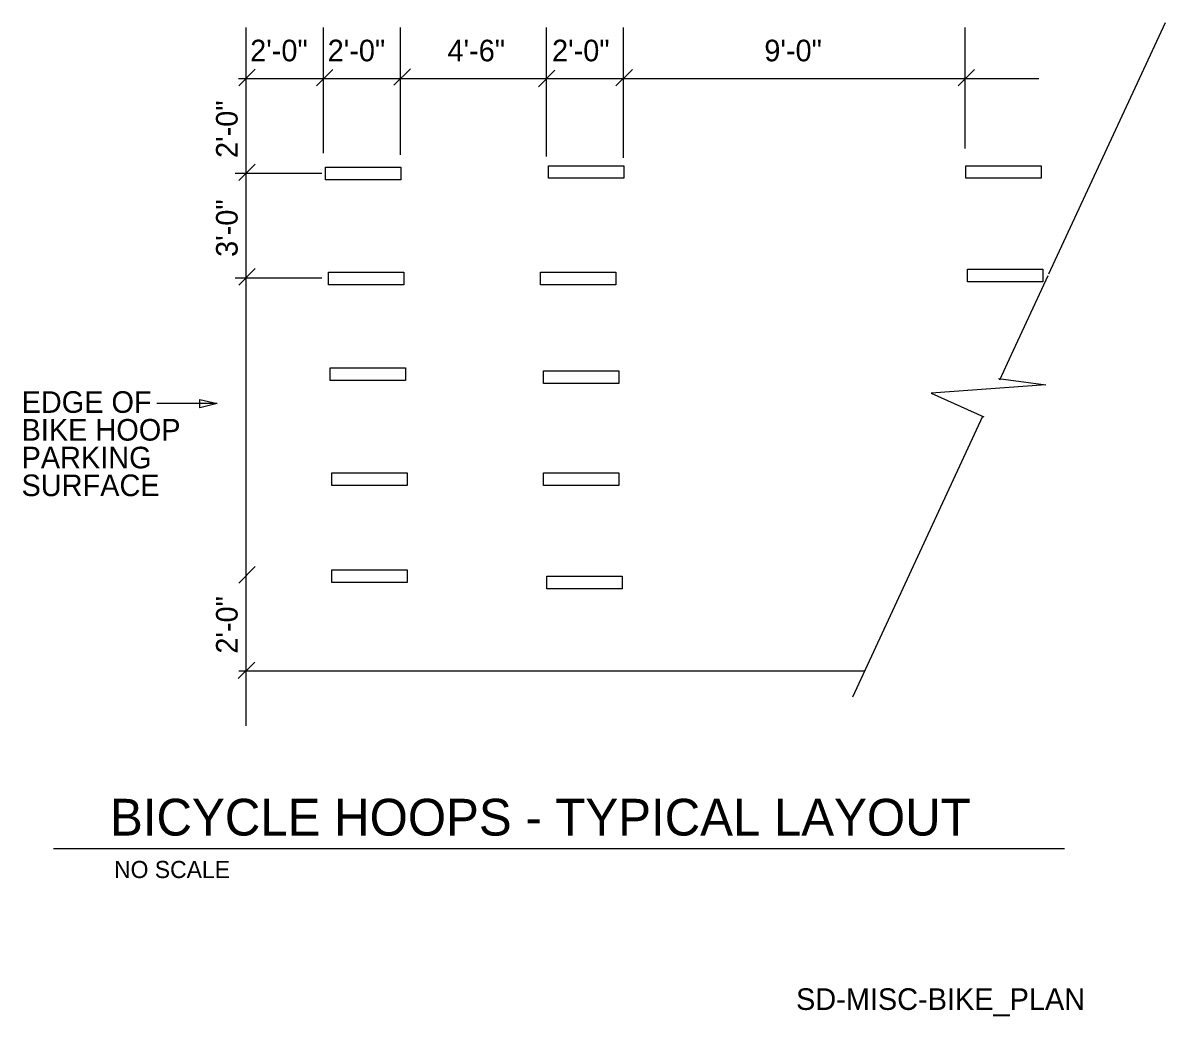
# Model space of a CAD drawing. Extents: x 10042.2 to 10097.3, y 10015.9 to 10063.9.
import ezdxf

# ---------------------------------------------------------------- set-up
doc = ezdxf.new("R2010")
doc.units = 0
for name, color, linetype in [('Default', 7, 'Continuous'), ('G-ANNO-TEXT', 7, 'Continuous'), ('G-DETL-LINE', 7, 'Continuous')]:
    doc.layers.add(name, color=color, linetype=linetype)

# ---------------------------------------------------------------- blocks, each defined once
blk = doc.blocks.new('TERARR')
at = {"layer": 'Default'}
blk.add_lwpolyline([(-0.667, 0.167), (0, 0), (-0.667, -0.167)], close=True, dxfattribs=at)

msp = doc.modelspace()

# ---------------------------------------------------------------- linework, layer by layer
at = {"layer": 'G-ANNO-TEXT'}
for p, q in [((10097.348, 10063.914), (10091.716, 10051.767)), ((10056.694, 10057.615), (10056.694, 10063.686)), ((10060.411, 10057.539), (10060.411, 10063.686)), ((10067.467, 10057.463), (10067.467, 10063.686)), ((10071.184, 10057.388), (10071.184, 10063.686)), ((10087.681, 10057.849), (10087.681, 10063.686)), ((10052.597, 10060.873), (10053.394, 10061.67)), ((10056.348, 10060.87), (10057.145, 10061.667)), ((10060.095, 10060.899), (10060.892, 10061.696)), ((10067.078, 10060.824), (10067.875, 10061.621)), ((10070.818, 10060.863), (10071.615, 10061.66)), ((10087.349, 10060.863), (10088.146, 10061.66)), ((10056.621, 10056.629), (10052.419, 10056.629)), ((10052.597, 10056.294), (10053.394, 10057.091)), ((10052.597, 10051.239), (10053.394, 10052.036)), ((10091.679, 10051.687), (10089.908, 10047.868)), ((10056.621, 10051.575), (10052.419, 10051.575)), ((10089.908, 10047.868), (10089.344, 10046.652)), ((10089.303, 10046.732), (10091.578, 10046.429)), ((10091.578, 10046.429), (10086.041, 10046.013)), ((10086.041, 10046.013), (10088.582, 10044.877)), ((10051.55, 10045.513), (10048.636, 10045.513)), ((10088.532, 10044.9), (10082.244, 10031.339)), ((10052.597, 10036.844), (10053.394, 10037.642)), ((10052.576, 10032.231), (10053.373, 10033.028)), ((10043.653, 10024.026), (10092.487, 10024.026))]:
    msp.add_line(p, q, dxfattribs=at)
at = {"layer": 'G-DETL-LINE'}
for p, q in [((10052.947, 10063.686), (10052.947, 10029.941)), ((10091.248, 10061.215), (10052.586, 10061.215)), ((10052.599, 10032.599), (10082.828, 10032.599))]:
    msp.add_line(p, q, dxfattribs=at)
for points in [[(10056.786, 10056.933), (10060.426, 10056.933), (10060.426, 10056.327), (10056.786, 10056.327)], [(10067.554, 10057.008), (10071.194, 10057.008), (10071.194, 10056.403), (10067.554, 10056.403)], [(10087.727, 10057.009), (10091.366, 10057.009), (10091.366, 10056.403), (10087.727, 10056.403)], [(10056.938, 10051.862), (10060.578, 10051.862), (10060.578, 10051.256), (10056.938, 10051.256)], [(10067.175, 10051.862), (10070.815, 10051.862), (10070.815, 10051.256), (10067.175, 10051.256)], [(10087.802, 10052.012), (10091.442, 10052.012), (10091.442, 10051.407), (10087.802, 10051.407)], [(10057.014, 10047.245), (10060.654, 10047.245), (10060.654, 10046.639), (10057.014, 10046.639)], [(10067.326, 10047.093), (10070.966, 10047.093), (10070.966, 10046.487), (10067.326, 10046.487)], [(10057.09, 10042.173), (10060.73, 10042.173), (10060.73, 10041.567), (10057.09, 10041.567)], [(10067.326, 10042.173), (10070.966, 10042.173), (10070.966, 10041.567), (10067.326, 10041.567)], [(10057.09, 10037.48), (10060.729, 10037.48), (10060.729, 10036.874), (10057.09, 10036.874)], [(10067.478, 10037.176), (10071.118, 10037.176), (10071.118, 10036.57), (10067.478, 10036.57)]]:
    msp.add_lwpolyline(points, close=True, dxfattribs=at)

# ---------------------------------------------------------------- block references
at = {"layer": 'G-ANNO-TEXT', "xscale": 1.24992, "yscale": 1.24992}
msp.add_blockref('TERARR', (10051.55, 10045.513), dxfattribs=at)

# ---------------------------------------------------------------- texts
at = {"layer": 'G-ANNO-TEXT'}
for s, height, p in [('2\'-0"', 1.044, (10053.152, 10062.054)), ('2\'-0"', 1.044, (10056.895, 10062.054)), ('4\'-6"', 1.044, (10062.683, 10062.054)), ('2\'-0"', 1.044, (10067.732, 10062.054)), ('9\'-0"', 1.044, (10077.987, 10062.054)), ('EDGE OF', 1.044, (10042.108, 10045.069)), ('BIKE HOOP', 1.044, (10042.108, 10043.728)), ('PARKING', 1.044, (10042.108, 10042.387)), ('SURFACE', 1.044, (10042.108, 10041.046)), ('BICYCLE HOOPS - TYPICAL LAYOUT', 1.776, (10046.383, 10024.644)), ('NO SCALE', 0.828, (10046.577, 10022.591)), ('SD-MISC-BIKE_PLAN', 1.044, (10079.518, 10016.22))]:
    msp.add_text(s, height=height, dxfattribs=at).set_placement(p)
for s, p in [('2\'-0"', (10052.546, 10057.383)), ('3\'-0"', (10052.546, 10052.604)), ('2\'-0"', (10052.546, 10033.434))]:
    msp.add_text(s, height=1.044, rotation=90, dxfattribs=at).set_placement(p)

doc.saveas('drawing.dxf')
